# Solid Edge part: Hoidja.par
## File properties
Author: Türk
Template: Iso Part.par
Last saved by: Türk
Revision: 32
Application: Solid Edge
Accuracy: 0,990
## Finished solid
Body 1: solid body, 45 faces, 105 edges, 58 vertices.
  Faces by surface: plane 25, cylinder 18, torus 2
  Edges by curve: line 69, circle 36
Bounding box of the edges (mm; curved faces can reach further): 221.000 x 108.000 x 233.000, from (-181, 0, -134) to (40, 108, 99).
Cylindrical faces by radius (mm): R4 x3, R5 x1, R10 x3, R10.5 x4, R18 x1, R25 x2, R30 x1, R32.5 x1, R40 x2
Toroidal faces (ring radius, tube radius in mm): R10.5 r2.5 x2
Planar faces by outward normal: +x 3, +y 2, +z 4, -x 4, -y 2, -z 4, oblique 6
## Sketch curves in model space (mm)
circle centre (0, 0, 0) radius 145.4166
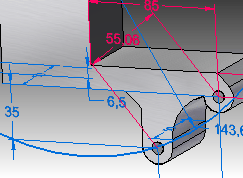
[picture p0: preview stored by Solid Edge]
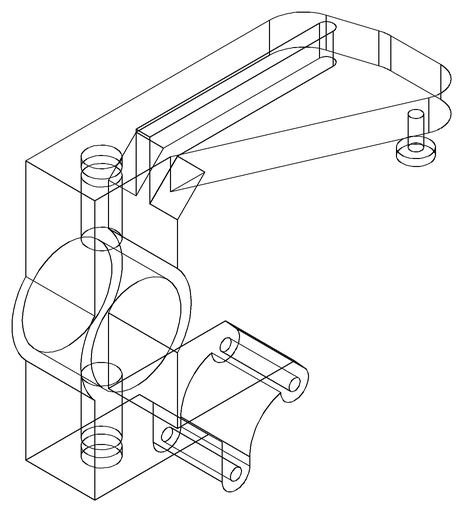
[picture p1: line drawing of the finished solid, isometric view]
